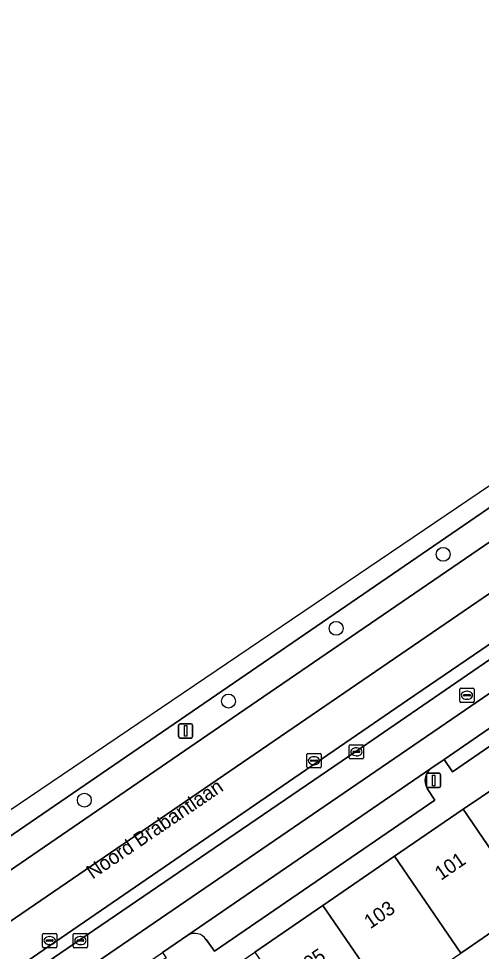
# Model space of a CAD drawing. Extents: x 158086 to 159499, y 382904 to 383981.
# Drawn here: x 158212.2 to 158244.8, y 383365.7 to 383431.3 of the extents above; entities that cross this region are included whole.
import ezdxf

# ---------------------------------------------------------------- set-up
doc = ezdxf.new("R2010")
doc.units = 0
for name, color, linetype in [('IMGEO_Berm_groen', 7, 'Continuous'), ('IMGEO_Boom', 7, 'Continuous'), ('IMGEO_Erf', 7, 'Continuous'), ('IMGEO_Fietspad_gesloten', 7, 'Continuous'), ('IMGEO_Groenvoorziening', 7, 'Continuous'), ('IMGEO_Haag', 7, 'Continuous'), ('IMGEO_Kolk', 7, 'Continuous'), ('IMGEO_Lichtmast', 7, 'Continuous'), ('IMGEO_Openbare_ruimte_label', 7, 'Continuous'), ('IMGEO_OVBaan_gesloten', 7, 'Continuous'), ('IMGEO_Pand', 7, 'Continuous'), ('IMGEO_Pand_nummerreeks', 7, 'Continuous'), ('IMGEO_Parkeervlak_open', 7, 'Continuous'), ('IMGEO_Rijbaan_lokaal_open', 7, 'Continuous'), ('IMGEO_Rijbaan_regionaal_gesloten', 7, 'Continuous'), ('IMGEO_Rioolput', 7, 'Continuous'), ('IMGEO_Voetpad_open', 7, 'Continuous')]:
    doc.layers.add(name, color=color, linetype=linetype)

msp = doc.modelspace()

# ---------------------------------------------------------------- linework, layer by layer
at = {"layer": 'IMGEO_Berm_groen'}
msp.add_lwpolyline([(158226.339, 383381.483), (158291.923, 383426.355), (158293.27, 383427.277), (158296.765, 383429.673), (158295.539, 383431.28), (158292.413, 383429.156), (158290.775, 383428.034), (158225.683, 383383.423), (158126.488, 383315.5), (158126.593, 383315.309), (158120.71, 383311.282), (158122.274, 383309.273), (158125.748, 383312.11), (158126.526, 383312.744), (158131.316, 383316.373), (158152.807, 383331.103)], close=True, dxfattribs=at)
at = {"layer": 'IMGEO_Boom'}
for centre in [(158242.081, 383393.611), (158234.552, 383388.404), (158226.969, 383383.292), (158216.833, 383376.32)]:
    msp.add_circle(centre, 0.489, dxfattribs=at)
at = {"layer": 'IMGEO_Erf'}
msp.add_lwpolyline([(158251.026, 383363.997), (158248.054, 383368.524), (158247.917, 383368.723), (158243.832, 383365.926), (158243.308, 383365.567)], dxfattribs=at)
at = {"layer": 'IMGEO_Fietspad_gesloten'}
for points in [[(158297.888, 383419.791), (158249.821, 383386.895), (158168.177, 383331.08), (158135.484, 383308.657), (158134.382, 383307.926)], [(158135.397, 383306.178), (158136.974, 383307.252), (158143.087, 383311.47), (158147.419, 383314.412), (158148.903, 383315.422), (158169.017, 383329.233), (158213.468, 383359.564), (158215.037, 383360.634), (158222.335, 383365.611), (158224.11, 383366.822), (158241.211, 383378.556), (158242.15, 383379.174), (158250.459, 383384.895), (158251.136, 383385.346), (158251.53, 383385.606), (158287.104, 383409.987)]]:
    msp.add_lwpolyline(points, dxfattribs=at)
at = {"layer": 'IMGEO_Groenvoorziening'}
for points in [[(158296.668, 383422.637), (158250.34, 383390.703), (158239.558, 383383.344), (158169.725, 383335.466), (158142.338, 383316.977), (158135.713, 383312.45), (158136.281, 383311.619), (158143.906, 383316.851), (158156.489, 383325.454), (158158.334, 383326.705), (158177.739, 383340.005), (158216.514, 383366.493)], [(158216.514, 383366.493), (158235.922, 383379.756), (158248.501, 383388.378), (158270.547, 383403.457), (158288.26, 383415.605), (158296.713, 383421.366)]]:
    msp.add_lwpolyline(points, dxfattribs=at)
at = {"layer": 'IMGEO_Haag'}
for points in [[(158296.668, 383422.637), (158250.34, 383390.703), (158239.558, 383383.344), (158169.725, 383335.466), (158142.338, 383316.977), (158135.713, 383312.45), (158136.281, 383311.619), (158143.906, 383316.851), (158156.489, 383325.454), (158158.334, 383326.705), (158177.739, 383340.005), (158216.514, 383366.493)], [(158216.514, 383366.493), (158235.922, 383379.756), (158248.501, 383388.378), (158270.547, 383403.457), (158288.26, 383415.605), (158296.713, 383421.366)]]:
    msp.add_lwpolyline(points, dxfattribs=at)
at = {"layer": 'IMGEO_Kolk'}
for p, q in [((158235.472, 383379.296), (158235.472, 383380.148)), ((158235.547, 383380.222), (158236.399, 383380.222)), ((158236.473, 383380.148), (158236.473, 383379.296)), ((158232.486, 383378.673), (158232.486, 383379.525)), ((158232.561, 383379.599), (158233.413, 383379.599)), ((158233.487, 383379.525), (158233.487, 383378.673)), ((158235.731, 383379.716), (158235.731, 383379.728)), ((158236.169, 383379.679), (158235.771, 383379.679)), ((158235.774, 383379.765), (158236.172, 383379.765)), ((158235.96, 383380.002), (158235.985, 383380.002)), ((158236.215, 383379.728), (158236.215, 383379.716)), ((158232.745, 383379.093), (158232.745, 383379.105)), ((158233.183, 383379.056), (158232.785, 383379.056)), ((158232.788, 383379.142), (158233.186, 383379.142)), ((158232.997, 383378.819), (158232.972, 383378.819)), ((158232.974, 383379.379), (158232.999, 383379.379)), ((158233.229, 383379.105), (158233.229, 383379.093)), ((158236.399, 383379.222), (158235.547, 383379.222)), ((158235.983, 383379.442), (158235.958, 383379.442)), ((158233.413, 383378.599), (158232.561, 383378.599)), ((158213.889, 383366.024), (158213.889, 383366.876)), ((158213.964, 383366.95), (158214.816, 383366.95)), ((158214.148, 383366.444), (158214.148, 383366.456)), ((158214.586, 383366.407), (158214.188, 383366.407)), ((158214.191, 383366.493), (158214.589, 383366.493)), ((158214.377, 383366.73), (158214.402, 383366.73)), ((158214.632, 383366.456), (158214.632, 383366.444)), ((158214.89, 383366.876), (158214.89, 383366.024)), ((158216.055, 383366.024), (158216.055, 383366.876)), ((158216.13, 383366.95), (158216.982, 383366.95)), ((158216.314, 383366.444), (158216.314, 383366.456)), ((158216.752, 383366.407), (158216.354, 383366.407)), ((158216.357, 383366.493), (158216.755, 383366.493)), ((158216.543, 383366.73), (158216.568, 383366.73)), ((158216.798, 383366.456), (158216.798, 383366.444)), ((158217.056, 383366.876), (158217.056, 383366.024)), ((158214.816, 383365.95), (158213.964, 383365.95)), ((158214.4, 383366.17), (158214.375, 383366.17)), ((158216.982, 383365.95), (158216.13, 383365.95)), ((158216.566, 383366.17), (158216.541, 383366.17))]:
    msp.add_line(p, q, dxfattribs=at)
for points in [[(158235.472, 383379.296), (158235.472, 383380.148)], [(158235.547, 383380.222), (158236.399, 383380.222)], [(158236.473, 383380.148), (158236.473, 383379.296)], [(158232.486, 383378.673), (158232.486, 383379.525)], [(158232.561, 383379.599), (158233.413, 383379.599)], [(158233.487, 383379.525), (158233.487, 383378.673)], [(158236.399, 383379.222), (158235.547, 383379.222)], [(158233.413, 383378.599), (158232.561, 383378.599)], [(158213.889, 383366.024), (158213.889, 383366.876)], [(158213.964, 383366.95), (158214.816, 383366.95)], [(158214.89, 383366.876), (158214.89, 383366.024)], [(158216.055, 383366.024), (158216.055, 383366.876)], [(158216.13, 383366.95), (158216.982, 383366.95)], [(158217.056, 383366.876), (158217.056, 383366.024)], [(158214.816, 383365.95), (158213.964, 383365.95)], [(158216.982, 383365.95), (158216.13, 383365.95)]]:
    msp.add_lwpolyline(points, dxfattribs=at)
for centre, radius, start, end in [((158235.549, 383380.146), 0.0765, 91.55205, 178.44795), ((158235.549, 383380.146), 0.0765, 91.55205, 178.44795), ((158236.397, 383380.146), 0.0765, 1.55205, 88.44795), ((158236.397, 383380.146), 0.0765, 1.55205, 88.44795), ((158232.563, 383379.523), 0.0765, 91.55205, 178.44795), ((158232.563, 383379.523), 0.0765, 91.55205, 178.44795), ((158233.411, 383379.523), 0.0765, 1.55205, 88.44795), ((158233.411, 383379.523), 0.0765, 1.55205, 88.44795), ((158235.771, 383379.725), 0.0403, 85.87752, 175.75265), ((158235.768, 383379.715), 0.0366, 178.93798, 274.71019), ((158236.172, 383379.722), 0.043, 264.86636, 352.45326), ((158236.176, 383379.727), 0.0386, 1.73085, 96.63898), ((158232.785, 383379.102), 0.0403, 85.87752, 175.75265), ((158232.782, 383379.092), 0.0366, 178.93798, 274.71019), ((158233.186, 383379.099), 0.043, 264.86636, 352.45326), ((158233.19, 383379.104), 0.0386, 1.73085, 96.63898), ((158235.549, 383379.298), 0.0765, 181.55205, 268.44795), ((158235.549, 383379.298), 0.0765, 181.55205, 268.44795), ((158236.397, 383379.298), 0.0765, 271.55205, 358.44795), ((158236.397, 383379.298), 0.0765, 271.55205, 358.44795), ((158232.563, 383378.675), 0.0765, 181.55205, 268.44795), ((158232.563, 383378.675), 0.0765, 181.55205, 268.44795), ((158233.411, 383378.675), 0.0765, 271.55205, 358.44795), ((158233.411, 383378.675), 0.0765, 271.55205, 358.44795), ((158213.966, 383366.874), 0.0765, 91.55205, 178.44795), ((158213.966, 383366.874), 0.0765, 91.55205, 178.44795), ((158214.188, 383366.453), 0.0403, 85.87752, 175.75265), ((158214.185, 383366.443), 0.0366, 178.93798, 274.71019), ((158214.589, 383366.45), 0.043, 264.86636, 352.45326), ((158214.593, 383366.455), 0.0386, 1.73085, 96.63898), ((158214.814, 383366.874), 0.0765, 1.55205, 88.44795), ((158214.814, 383366.874), 0.0765, 1.55205, 88.44795), ((158216.132, 383366.874), 0.0765, 91.55205, 178.44795), ((158216.132, 383366.874), 0.0765, 91.55205, 178.44795), ((158216.354, 383366.453), 0.0403, 85.87752, 175.75265), ((158216.351, 383366.443), 0.0366, 178.93798, 274.71019), ((158216.755, 383366.45), 0.043, 264.86636, 352.45326), ((158216.759, 383366.455), 0.0386, 1.73085, 96.63898), ((158216.98, 383366.874), 0.0765, 1.55205, 88.44795), ((158216.98, 383366.874), 0.0765, 1.55205, 88.44795), ((158213.966, 383366.026), 0.0765, 181.55205, 268.44795), ((158213.966, 383366.026), 0.0765, 181.55205, 268.44795), ((158214.814, 383366.026), 0.0765, 271.55205, 358.44795), ((158214.814, 383366.026), 0.0765, 271.55205, 358.44795), ((158216.132, 383366.026), 0.0765, 181.55205, 268.44795), ((158216.132, 383366.026), 0.0765, 181.55205, 268.44795), ((158216.98, 383366.026), 0.0765, 271.55205, 358.44795), ((158216.98, 383366.026), 0.0765, 271.55205, 358.44795)]:
    msp.add_arc(centre, radius, start, end, dxfattribs=at)
for centre, major_axis, ratio, start_param, end_param in [((158235.959, 383379.722), (-0.387, 0.002), 0.722429, 4.712389, 7.853982), ((158235.984, 383379.722), (-0.39, 0.002), 0.717154, 1.570796, 4.712389), ((158232.973, 383379.099), (-0.387, 0.002), 0.722429, 4.712389, 7.853982), ((158232.998, 383379.099), (-0.39, 0.002), 0.717154, 1.570796, 4.712389), ((158214.376, 383366.45), (-0.387, 0.002), 0.722429, 4.712389, 7.853982), ((158214.401, 383366.45), (-0.39, 0.002), 0.717154, 1.570796, 4.712389), ((158216.542, 383366.45), (-0.387, 0.002), 0.722429, 4.712389, 7.853982), ((158216.567, 383366.45), (-0.39, 0.002), 0.717154, 1.570796, 4.712389)]:
    msp.add_ellipse(centre, major_axis=major_axis, ratio=ratio, start_param=start_param, end_param=end_param, dxfattribs=at)
at = {"layer": 'IMGEO_Lichtmast'}
for p, q in [((158223.461, 383380.79), (158223.461, 383381.59)), ((158223.461, 383381.59), (158223.461, 383380.79)), ((158223.561, 383381.69), (158224.351, 383381.69)), ((158224.351, 383381.69), (158223.561, 383381.69)), ((158224.451, 383381.59), (158224.451, 383380.79)), ((158224.451, 383380.79), (158224.451, 383381.59)), ((158224.351, 383380.69), (158223.561, 383380.69)), ((158223.561, 383380.69), (158224.351, 383380.69)), ((158241.008, 383378.212), (158241.798, 383378.212)), ((158241.798, 383378.212), (158241.008, 383378.212)), ((158240.908, 383377.312), (158240.908, 383378.112)), ((158240.908, 383378.112), (158240.908, 383377.312)), ((158241.898, 383378.112), (158241.898, 383377.312)), ((158241.898, 383377.312), (158241.898, 383378.112)), ((158241.798, 383377.212), (158241.008, 383377.212)), ((158241.008, 383377.212), (158241.798, 383377.212))]:
    msp.add_line(p, q, dxfattribs=at)
for points in [[(158223.881, 383381.565), (158224.031, 383381.565), (158224.031, 383380.815), (158223.881, 383380.815), (158223.881, 383381.565)], [(158241.328, 383378.087), (158241.478, 383378.087), (158241.478, 383377.337), (158241.328, 383377.337), (158241.328, 383378.087)]]:
    msp.add_lwpolyline(points, dxfattribs=at)
for centre, start, end in [((158223.561, 383381.59), 90, 180), ((158223.561, 383381.59), 90, 180), ((158224.351, 383381.59), 0, 90), ((158224.351, 383381.59), 360, 90), ((158223.561, 383380.79), 180, 270), ((158223.561, 383380.79), 180, 270), ((158224.351, 383380.79), 270, 0), ((158224.351, 383380.79), 270, 0), ((158241.008, 383378.112), 90, 180), ((158241.008, 383378.112), 90, 180), ((158241.798, 383378.112), 0, 90), ((158241.798, 383378.112), 360, 90), ((158241.008, 383377.312), 180, 270), ((158241.008, 383377.312), 180, 270), ((158241.798, 383377.312), 270, 0), ((158241.798, 383377.312), 270, 0)]:
    msp.add_arc(centre, 0.1, start, end, dxfattribs=at)
at = {"layer": 'IMGEO_OVBaan_gesloten'}
msp.add_lwpolyline([(158290.829, 383429.195), (158142.057, 383328.583), (158135.353, 383324.049), (158105.383, 383303.781), (158106.799, 383301.782), (158111.95, 383305.28), (158120.71, 383311.282), (158126.593, 383315.309), (158126.488, 383315.5), (158225.683, 383383.423), (158290.775, 383428.034)], dxfattribs=at)
at = {"layer": 'IMGEO_Pand'}
for points in [[(158238.647, 383372.376), (158243.308, 383365.567), (158243.832, 383365.926), (158247.917, 383368.723), (158248.054, 383368.524), (158248.263, 383368.693), (158243.473, 383375.686)], [(158238.647, 383372.376), (158233.612, 383368.922), (158238.269, 383362.117), (158243.308, 383365.567)], [(158238.269, 383362.117), (158233.612, 383368.922), (158228.836, 383365.646), (158233.49, 383358.846)]]:
    msp.add_lwpolyline(points, close=True, dxfattribs=at)
at = {"layer": 'IMGEO_Parkeervlak_open'}
for points in [[(158241.211, 383378.556), (158224.11, 383366.822)], [(158225.407, 383366.514), (158225.983, 383365.702), (158241.501, 383376.328), (158240.956, 383377.149)]]:
    msp.add_lwpolyline(points, dxfattribs=at)
for centre, radius, start, end in [((158241.859, 383377.712), 1.064, 127.51414, 211.94068), ((158224.601, 383366.003), 0.954, 32.34608, 120.93661)]:
    msp.add_arc(centre, radius, start, end, dxfattribs=at)
at = {"layer": 'IMGEO_Rijbaan_lokaal_open'}
for points in [[(158135.494, 383309.526), (158135.588, 383309.03), (158135.484, 383308.657), (158168.177, 383331.08), (158249.821, 383386.895), (158297.888, 383419.791), (158299.772, 383421.047), (158299.394, 383421.023), (158298.978, 383421.305)], [(158296.713, 383421.366), (158288.26, 383415.605), (158270.547, 383403.457), (158248.501, 383388.378), (158235.922, 383379.756), (158216.514, 383366.493), (158177.739, 383340.005), (158158.334, 383326.705), (158156.489, 383325.454), (158143.906, 383316.851), (158136.281, 383311.619)]]:
    msp.add_lwpolyline(points, dxfattribs=at)
at = {"layer": 'IMGEO_Rijbaan_regionaal_gesloten'}
for points in [[(158291.923, 383426.355), (158226.339, 383381.483), (158152.807, 383331.103), (158131.316, 383316.373), (158126.526, 383312.744), (158125.748, 383312.11), (158122.274, 383309.273), (158117.034, 383305.405), (158108.377, 383299.51), (158110.059, 383297.015), (158120.725, 383304.43), (158130.088, 383311.713), (158140.153, 383318.963), (158150.139, 383325.717), (158153.45, 383328.028), (158163.611, 383334.93), (158173.4, 383341.65), (158180.047, 383346.206), (158193.317, 383355.261), (158200.003, 383359.875), (158206.611, 383364.391), (158296.442, 383425.805)], [(158296.442, 383425.805), (158206.611, 383364.391), (158200.003, 383359.875), (158193.317, 383355.261), (158180.047, 383346.206), (158173.4, 383341.65), (158163.611, 383334.93), (158153.45, 383328.028), (158150.139, 383325.717), (158140.153, 383318.963), (158130.088, 383311.713), (158120.725, 383304.43), (158110.059, 383297.015), (158111.752, 383294.502), (158116.714, 383297.886), (158119.385, 383299.725), (158121.038, 383300.856), (158122.649, 383302.057), (158124.994, 383303.909), (158127.323, 383305.803), (158128.269, 383306.604)], [(158135.533, 383312.327), (158135.713, 383312.45), (158142.338, 383316.977), (158169.725, 383335.466), (158239.558, 383383.344), (158250.34, 383390.703), (158296.668, 383422.637)]]:
    msp.add_lwpolyline(points, dxfattribs=at)
at = {"layer": 'IMGEO_Rioolput'}
for p, q in [((158243.248, 383383.274), (158243.248, 383384.126)), ((158243.323, 383384.2), (158244.175, 383384.2)), ((158244.249, 383384.126), (158244.249, 383383.274)), ((158243.507, 383383.694), (158243.507, 383383.706)), ((158243.945, 383383.657), (158243.547, 383383.657)), ((158243.55, 383383.743), (158243.948, 383383.743)), ((158243.759, 383383.42), (158243.734, 383383.42)), ((158243.736, 383383.98), (158243.761, 383383.98)), ((158243.991, 383383.706), (158243.991, 383383.694)), ((158244.175, 383383.2), (158243.323, 383383.2))]:
    msp.add_line(p, q, dxfattribs=at)
for points in [[(158243.248, 383383.274), (158243.248, 383384.126)], [(158243.323, 383384.2), (158244.175, 383384.2)], [(158244.249, 383384.126), (158244.249, 383383.274)], [(158244.175, 383383.2), (158243.323, 383383.2)]]:
    msp.add_lwpolyline(points, dxfattribs=at)
for centre, radius, start, end in [((158243.325, 383384.124), 0.0765, 91.55205, 178.44795), ((158243.325, 383384.124), 0.0765, 91.55205, 178.44795), ((158244.173, 383384.124), 0.0765, 1.55205, 88.44795), ((158244.173, 383384.124), 0.0765, 1.55205, 88.44795), ((158243.547, 383383.703), 0.0403, 85.87752, 175.75265), ((158243.544, 383383.693), 0.0366, 178.93798, 274.71019), ((158243.948, 383383.7), 0.043, 264.86636, 352.45326), ((158243.952, 383383.705), 0.0386, 1.73085, 96.63898), ((158243.325, 383383.276), 0.0765, 181.55205, 268.44795), ((158243.325, 383383.276), 0.0765, 181.55205, 268.44795), ((158244.173, 383383.276), 0.0765, 271.55205, 358.44795), ((158244.173, 383383.276), 0.0765, 271.55205, 358.44795)]:
    msp.add_arc(centre, radius, start, end, dxfattribs=at)
for centre, major_axis, ratio, start_param, end_param in [((158243.735, 383383.7), (-0.387, 0.002), 0.722429, 4.712389, 7.853982), ((158243.76, 383383.7), (-0.39, 0.002), 0.717154, 1.570796, 4.712389)]:
    msp.add_ellipse(centre, major_axis=major_axis, ratio=ratio, start_param=start_param, end_param=end_param, dxfattribs=at)
at = {"layer": 'IMGEO_Voetpad_open'}
for points in [[(158233.612, 383368.922), (158238.647, 383372.376), (158243.473, 383375.686), (158246.003, 383377.378), (158248.588, 383379.097), (158251.587, 383381.214), (158253.742, 383382.72), (158258.741, 383386.142), (158263.546, 383389.432), (158268.332, 383392.709), (158273.136, 383395.998), (158277.79, 383399.184), (158282.682, 383402.534), (158287.37, 383405.743), (158292.28, 383409.105), (158296.89, 383412.261), (158298.48, 383413.344), (158302.59, 383416.143), (158301.124, 383418.292), (158293.57, 383413.139), (158292.984, 383413.998), (158287.104, 383409.987)], [(158251.53, 383385.606), (158251.136, 383385.346), (158250.459, 383384.895), (158251.049, 383384.038), (158242.74, 383378.317), (158242.15, 383379.174), (158241.211, 383378.556)], [(158240.956, 383377.149), (158241.501, 383376.328), (158225.983, 383365.702), (158225.407, 383366.514)], [(158246.003, 383377.378), (158243.473, 383375.686), (158248.263, 383368.693), (158248.054, 383368.524), (158251.026, 383363.997), (158250.892, 383362.545), (158250.39, 383355.99), (158250.387, 383355.956), (158250.128, 383353.89), (158249.12, 383345.719), (158248.754, 383342.754), (158244.969, 383312.049), (158244.858, 383311.152), (158244.558, 383308.736), (158243.427, 383301.176), (158242.318, 383292.241), (158242.045, 383290.194)], [(158150.25, 383311.92), (158155.491, 383315.503), (158160.257, 383318.762), (158165.024, 383322.021), (158169.792, 383325.281), (158174.559, 383328.54), (158179.326, 383331.799), (158184.097, 383335.061), (158188.869, 383338.324), (158193.64, 383341.586), (158198.411, 383344.848), (158203.182, 383348.11), (158207.953, 383351.372), (158212.725, 383354.634), (158217.541, 383357.927), (158220.677, 383360.064), (158222.111, 383361.041), (158223.951, 383362.295), (158228.836, 383365.646), (158233.612, 383368.922)], [(158224.11, 383366.822), (158222.335, 383365.611), (158222.588, 383365.239), (158215.292, 383360.263), (158215.037, 383360.634), (158213.468, 383359.564)]]:
    msp.add_lwpolyline(points, dxfattribs=at)
msp.add_lwpolyline([(158250.459, 383384.895), (158242.15, 383379.174), (158242.74, 383378.317), (158251.049, 383384.038)], close=True, dxfattribs=at)
for centre, radius, start, end in [((158241.859, 383377.712), 1.064, 127.51414, 211.94068), ((158224.601, 383366.003), 0.954, 32.34608, 120.93661)]:
    msp.add_arc(centre, radius, start, end, dxfattribs=at)

# ---------------------------------------------------------------- texts
at = {"layer": 'IMGEO_Openbare_ruimte_label'}
msp.add_text('Noord Brabantlaan', height=1, rotation=34.19864, dxfattribs=at).set_placement((158217.409, 383370.735))
at = {"layer": 'IMGEO_Pand_nummerreeks'}
for s, p in [('101', (158241.92, 383370.644)), ('103', (158236.946, 383367.232)), ('105', (158232.065, 383363.884))]:
    msp.add_text(s, height=1, rotation=34.44794, dxfattribs=at).set_placement(p)

doc.saveas('drawing.dxf')
